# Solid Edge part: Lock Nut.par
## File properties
Author: Deepak Maini
Template: normal.par
Last saved by: Administrator
Revision: 4
Application: Solid Edge
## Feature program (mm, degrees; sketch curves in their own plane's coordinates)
sketch for "unnamed Protrusion 1" plane through (0, 0, 0) normal (0, 0, 1) x-axis (1, 0, 0)
  line (-7.5, 12.9904) -> (-15, 0)
  line (-15, 0) -> (-7.5, -12.9904)
  line (-7.5, -12.9904) -> (7.5, -12.9904)
  line (7.5, -12.9904) -> (15, 0)
  line (15, 0) -> (7.5, 12.9904)
  line (7.5, 12.9904) -> (-7.5, 12.9904)
extrude "unnamed Protrusion 1" add finite 8 symmetric
sketch for "unnamed RevolvedCutout 1" plane through (0, 0, 0) normal (0, -1, 0) x-axis (1, 0, 0)
  arc centre (12, 1) radius 3 from (12, 4) to (15, 1) cw
  line (15, 4) -> (15, 1)
  line (15, 4) -> (12, 4)
revolve "unnamed RevolvedCutout 1" cut full turn 360 deg
mirror "unnamed Mirror 1" of "unnamed RevolvedCutout 1" about plane through (0, 0, 0) normal (0, 0, 1)
revolve "unnamed RevolvedCutout 2" cut full turn 360 deg
sketch for "unnamed Hole 1" plane through (0, 0, 4) normal (0, 0, 1) x-axis (0, 1, 0)
  hole centre (0, 0) bore radius 6
hole "unnamed Hole 1" through
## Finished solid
Body 1: solid body, 11 faces, 22 edges, 12 vertices.
  Faces by surface: plane 8, torus 2, cylinder 1
  Edges by curve: intersection 12, line 6, circle 4
Bounding box of the edges (mm; curved faces can reach further): 30.000 x 25.981 x 8.000, from (-15, -12.9904, -4) to (15, 12.9904, 4).
Cylindrical faces by radius (mm): R6 x1
Toroidal faces (ring radius, tube radius in mm): R12 r3 x2
Planar faces by outward normal: +y 1, +z 1, -y 1, -z 1, oblique 4
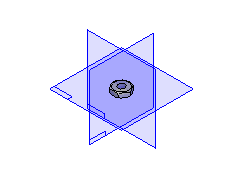
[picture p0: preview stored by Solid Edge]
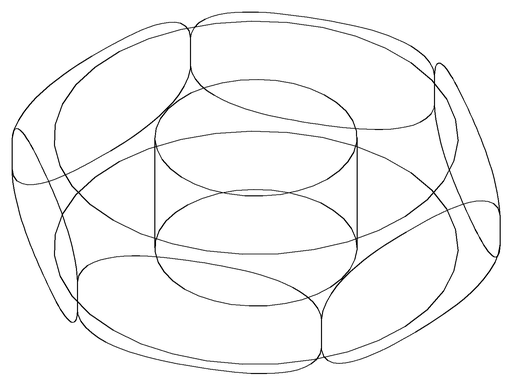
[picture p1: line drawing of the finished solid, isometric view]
